(* Logix 5000 project; controller DNP3Master vendor 1 type 14 code 96 rev 19.13; software revision 19.01; part 2 of 5 *)

ADD_ON_INSTRUCTION PSDNP3EventG20V02   (* revision 1.0, vendor ProSoft Technology Inc *)
// Processes DNP3 Event and updates corresponding static DNP3 object. (Report by Exception.)
// G20V02 - Counter - 16bit with Status
VAR_IN_OUT
   EventBuffer : PSDNP3MasterEvent[1]; {required}
END_VAR
VAR_INPUT
   BufferSize : DINT; {required}
   CurrentBufferIndex : DINT; {required}
   Reset : BOOL; {required}
   OutstationNodeAddress : INT; {required}
   OutstationIPAddress0 : INT; {required}
   OutstationIPAddress1 : INT; {required}
   OutstationIPAddress2 : INT; {required}
   OutstationIPAddress3 : INT; {required}
END_VAR
VAR_IN_OUT
   DNP3StaticObject : PSDNP3Counter16WithFlag[1]; {required}
END_VAR
VAR_INPUT
   MaxtElementCount : DINT; {required}
END_VAR
VAR_OUTPUT
   EventsProcessed : DINT; {access Read Only, visible}
   LastElementIndex : DINT; {access Read Only, visible}
   LastValue : DINT; {access Read Only, visible}
   LastStatus : SINT; {access Read Only, visible}
   CurrentUnloadIndex : DINT; {access Read Only, visible}
END_VAR
VAR
   UnloadIndex : DINT; {access None}
   EnableInTemp : BOOL; {access None}
   InitialScan : BOOL; {access None}
   EntryValidForProcessing : BOOL; {access None}
   ElementIndex : DINT; {access None}
   NextIndex : DINT; {access None}
   ResetPulse : BOOL; {access None}
   ResetONS : BOOL; {access None}
END_VAR

ROUTINE Logic   (* ladder *)
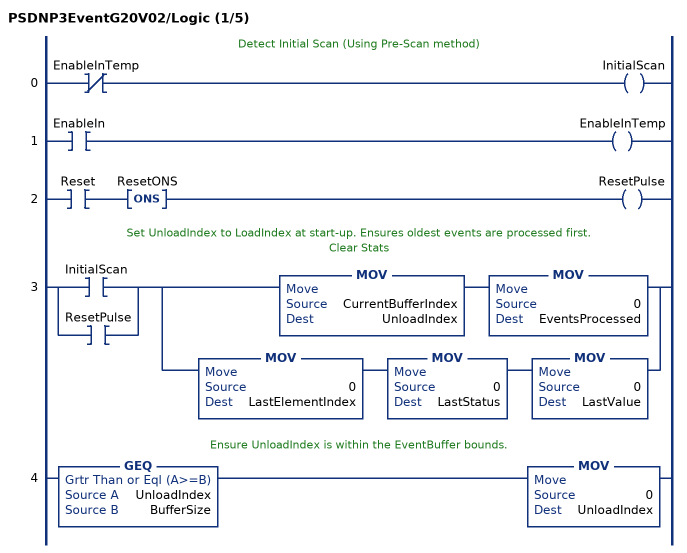
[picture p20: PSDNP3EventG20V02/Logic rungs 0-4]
   // Detect Initial Scan (Using Pre-Scan method)
   0: XIO(EnableInTemp)OTE(InitialScan);
   1: XIC(EnableIn)OTE(EnableInTemp);
   2: XIC(Reset)ONS(ResetONS)OTE(ResetPulse);
   // Set UnloadIndex to LoadIndex at start-up. Ensures oldest events are processed first.
   // Clear Stats
   3: [XIC(InitialScan) ,XIC(ResetPulse) ][MOV(CurrentBufferIndex,UnloadIndex) MOV(0,EventsProcessed) ,MOV(0,LastElementIndex) MOV(0,LastStatus) MOV(0,LastValue) ];
   // Ensure UnloadIndex is within the EventBuffer bounds.
   4: GEQ(UnloadIndex,BufferSize)MOV(0,UnloadIndex);
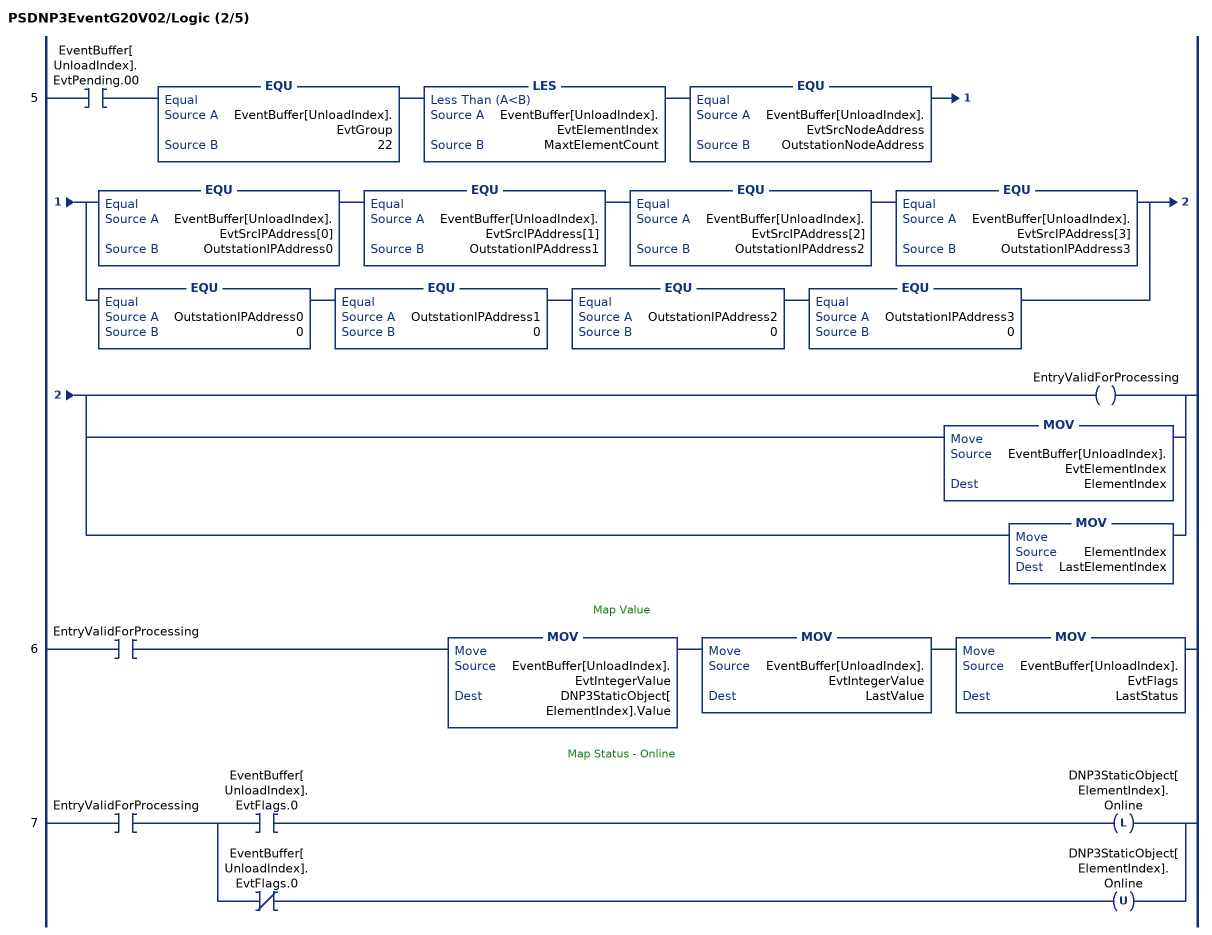
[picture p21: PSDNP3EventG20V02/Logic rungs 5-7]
   5: XIC(EventBuffer[UnloadIndex].EvtPending.00)EQU(EventBuffer[UnloadIndex].EvtGroup,22)LES(EventBuffer[UnloadIndex].EvtElementIndex,MaxtElementCount)EQU(EventBuffer[UnloadIndex].EvtSrcNodeAddress,OutstationNodeAddress)[EQU(EventBuffer[UnloadIndex].EvtSrcIPAddress[0],OutstationIPAddress0) EQU(EventBuffer[UnloadIndex].EvtSrcIPAddress[1],OutstationIPAddress1) EQU(EventBuffer[UnloadIndex].EvtSrcIPAddress[2],OutstationIPAddress2) EQU(EventBuffer[UnloadIndex].EvtSrcIPAddress[3],OutstationIPAddress3) ,EQU(OutstationIPAddress0,0) EQU(OutstationIPAddress1,0) EQU(OutstationIPAddress2,0) EQU(OutstationIPAddress3,0) ][OTE(EntryValidForProcessing) ,MOV(EventBuffer[UnloadIndex].EvtElementIndex,ElementIndex) ,MOV(ElementIndex,LastElementIndex) ];
   // Map Value
   6: XIC(EntryValidForProcessing)MOV(EventBuffer[UnloadIndex].EvtIntegerValue,DNP3StaticObject[ElementIndex].Value)MOV(EventBuffer[UnloadIndex].EvtIntegerValue,LastValue)MOV(EventBuffer[UnloadIndex].EvtFlags,LastStatus);
   // Map Status - Online
   7: XIC(EntryValidForProcessing)[XIC(EventBuffer[UnloadIndex].EvtFlags.0) OTL(DNP3StaticObject[ElementIndex].Online) ,XIO(EventBuffer[UnloadIndex].EvtFlags.0) OTU(DNP3StaticObject[ElementIndex].Online) ];
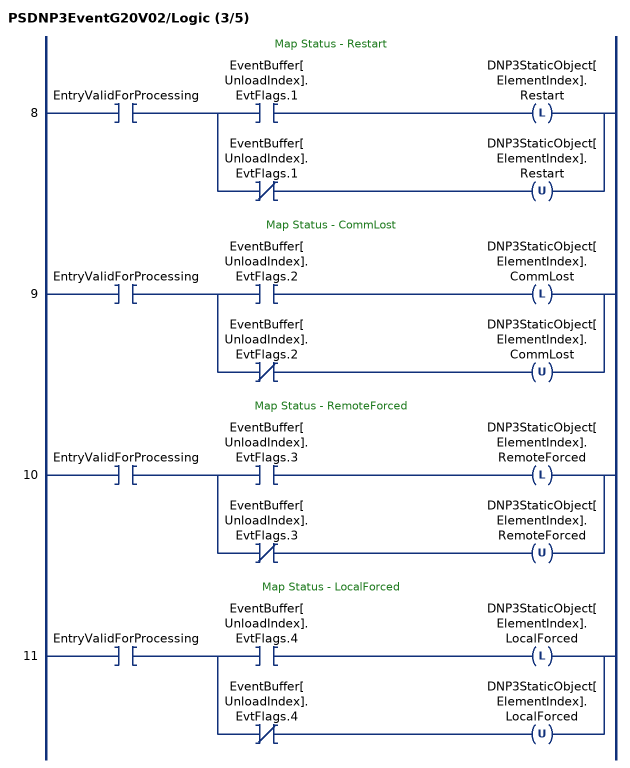
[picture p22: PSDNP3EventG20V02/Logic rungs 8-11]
   // Map Status - Restart
   8: XIC(EntryValidForProcessing)[XIC(EventBuffer[UnloadIndex].EvtFlags.1) OTL(DNP3StaticObject[ElementIndex].Restart) ,XIO(EventBuffer[UnloadIndex].EvtFlags.1) OTU(DNP3StaticObject[ElementIndex].Restart) ];
   // Map Status - CommLost
   9: XIC(EntryValidForProcessing)[XIC(EventBuffer[UnloadIndex].EvtFlags.2) OTL(DNP3StaticObject[ElementIndex].CommLost) ,XIO(EventBuffer[UnloadIndex].EvtFlags.2) OTU(DNP3StaticObject[ElementIndex].CommLost) ];
   // Map Status - RemoteForced
   10: XIC(EntryValidForProcessing)[XIC(EventBuffer[UnloadIndex].EvtFlags.3) OTL(DNP3StaticObject[ElementIndex].RemoteForced) ,XIO(EventBuffer[UnloadIndex].EvtFlags.3) OTU(DNP3StaticObject[ElementIndex].RemoteForced) ];
   // Map Status - LocalForced
   11: XIC(EntryValidForProcessing)[XIC(EventBuffer[UnloadIndex].EvtFlags.4) OTL(DNP3StaticObject[ElementIndex].LocalForced) ,XIO(EventBuffer[UnloadIndex].EvtFlags.4) OTU(DNP3StaticObject[ElementIndex].LocalForced) ];
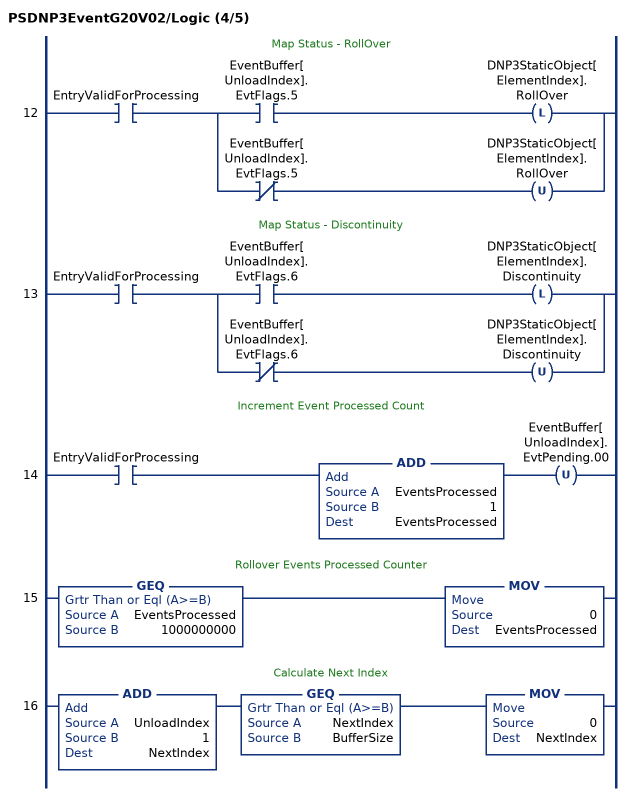
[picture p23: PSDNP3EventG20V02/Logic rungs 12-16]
   // Map Status - RollOver
   12: XIC(EntryValidForProcessing)[XIC(EventBuffer[UnloadIndex].EvtFlags.5) OTL(DNP3StaticObject[ElementIndex].RollOver) ,XIO(EventBuffer[UnloadIndex].EvtFlags.5) OTU(DNP3StaticObject[ElementIndex].RollOver) ];
   // Map Status - Discontinuity
   13: XIC(EntryValidForProcessing)[XIC(EventBuffer[UnloadIndex].EvtFlags.6) OTL(DNP3StaticObject[ElementIndex].Discontinuity) ,XIO(EventBuffer[UnloadIndex].EvtFlags.6) OTU(DNP3StaticObject[ElementIndex].Discontinuity) ];
   // Increment Event Processed Count
   14: XIC(EntryValidForProcessing)ADD(EventsProcessed,1,EventsProcessed)OTU(EventBuffer[UnloadIndex].EvtPending.00);
   // Rollover Events Processed Counter
   15: GEQ(EventsProcessed,1000000000)MOV(0,EventsProcessed);
   // Calculate Next Index
   16: ADD(UnloadIndex,1,NextIndex)GEQ(NextIndex,BufferSize)MOV(0,NextIndex);
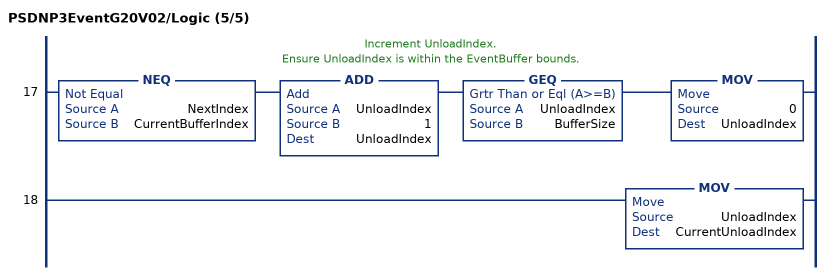
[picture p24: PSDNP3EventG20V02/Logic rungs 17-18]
   // Increment UnloadIndex.
   // Ensure UnloadIndex is within the EventBuffer bounds.
   17: NEQ(NextIndex,CurrentBufferIndex)ADD(UnloadIndex,1,UnloadIndex)GEQ(UnloadIndex,BufferSize)MOV(0,UnloadIndex);
   18: MOV(UnloadIndex,CurrentUnloadIndex);
END_ROUTINE
END_ADD_ON_INSTRUCTION

ADD_ON_INSTRUCTION PSDNP3EventG20V05   (* revision 1.0, vendor ProSoft Technology Inc *)
// Processes DNP3 Event and updates corresponding static DNP3 object. (Report by Exception.)
// G20V05 - Counter - 32bit no Status
VAR_IN_OUT
   EventBuffer : PSDNP3MasterEvent[1]; {required}
END_VAR
VAR_INPUT
   BufferSize : DINT; {required}
   CurrentBufferIndex : DINT; {required}
   Reset : BOOL; {required}
   OutstationNodeAddress : INT; {required}
   OutstationIPAddress0 : INT; {required}
   OutstationIPAddress1 : INT; {required}
   OutstationIPAddress2 : INT; {required}
   OutstationIPAddress3 : INT; {required}
END_VAR
VAR_IN_OUT
   DNP3StaticObject : DINT[1]; {required}
END_VAR
VAR_INPUT
   MaxtElementCount : DINT; {required}
END_VAR
VAR_OUTPUT
   EventsProcessed : DINT; {access Read Only, visible}
   LastElementIndex : DINT; {access Read Only, visible}
   LastValue : DINT; {access Read Only, visible}
   LastStatus : SINT; {access Read Only, visible}
   CurrentUnloadIndex : DINT; {access Read Only, visible}
END_VAR
VAR
   UnloadIndex : DINT; {access None}
   EnableInTemp : BOOL; {access None}
   InitialScan : BOOL; {access None}
   EntryValidForProcessing : BOOL; {access None}
   ElementIndex : DINT; {access None}
   NextIndex : DINT; {access None}
   ResetPulse : BOOL; {access None}
   ResetONS : BOOL; {access None}
END_VAR

ROUTINE Logic   (* ladder *)
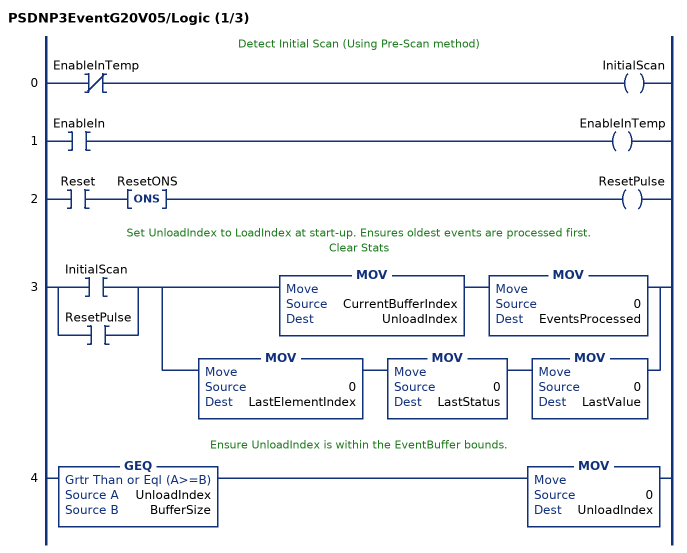
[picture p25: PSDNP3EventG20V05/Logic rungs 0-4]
   // Detect Initial Scan (Using Pre-Scan method)
   0: XIO(EnableInTemp)OTE(InitialScan);
   1: XIC(EnableIn)OTE(EnableInTemp);
   2: XIC(Reset)ONS(ResetONS)OTE(ResetPulse);
   // Set UnloadIndex to LoadIndex at start-up. Ensures oldest events are processed first.
   // Clear Stats
   3: [XIC(InitialScan) ,XIC(ResetPulse) ][MOV(CurrentBufferIndex,UnloadIndex) MOV(0,EventsProcessed) ,MOV(0,LastElementIndex) MOV(0,LastStatus) MOV(0,LastValue) ];
   // Ensure UnloadIndex is within the EventBuffer bounds.
   4: GEQ(UnloadIndex,BufferSize)MOV(0,UnloadIndex);
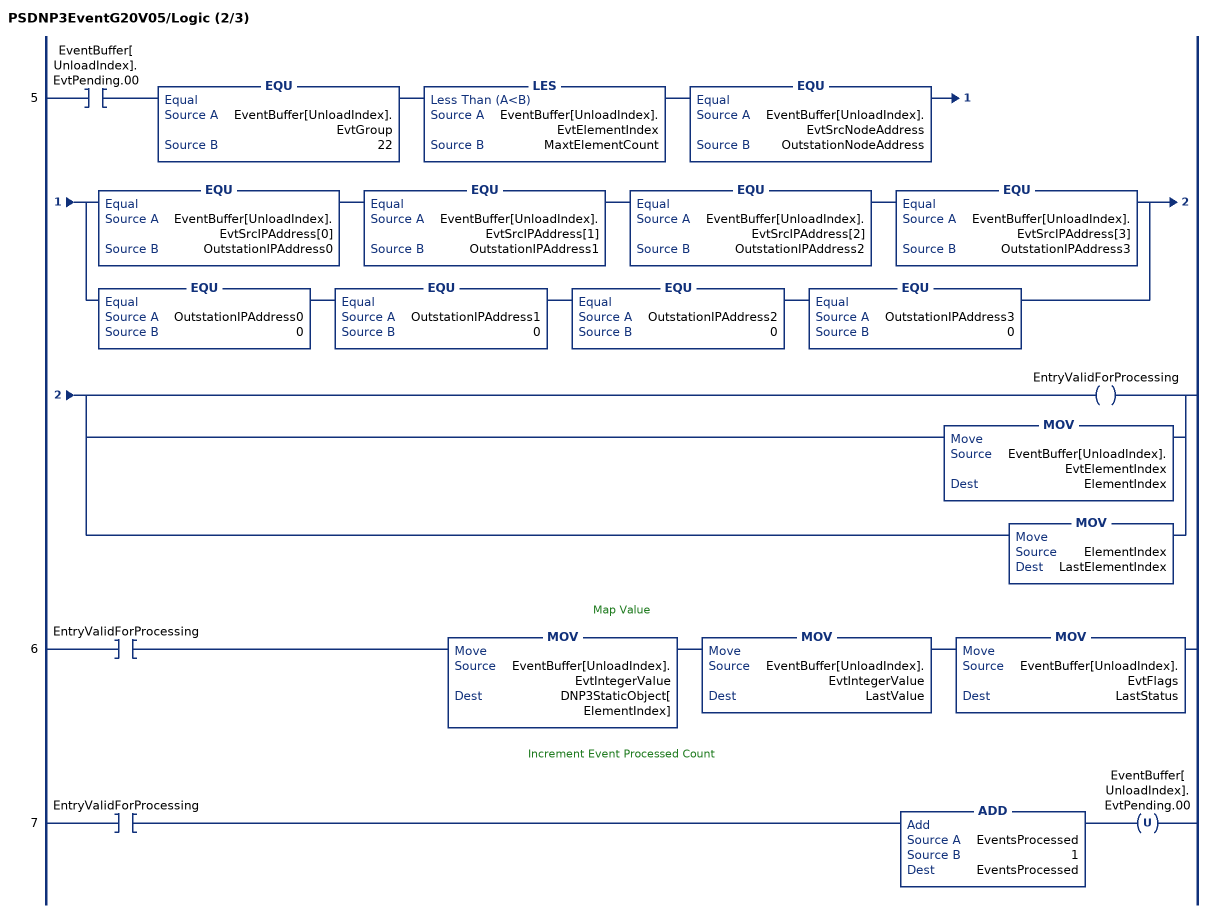
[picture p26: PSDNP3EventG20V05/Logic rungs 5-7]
   5: XIC(EventBuffer[UnloadIndex].EvtPending.00)EQU(EventBuffer[UnloadIndex].EvtGroup,22)LES(EventBuffer[UnloadIndex].EvtElementIndex,MaxtElementCount)EQU(EventBuffer[UnloadIndex].EvtSrcNodeAddress,OutstationNodeAddress)[EQU(EventBuffer[UnloadIndex].EvtSrcIPAddress[0],OutstationIPAddress0) EQU(EventBuffer[UnloadIndex].EvtSrcIPAddress[1],OutstationIPAddress1) EQU(EventBuffer[UnloadIndex].EvtSrcIPAddress[2],OutstationIPAddress2) EQU(EventBuffer[UnloadIndex].EvtSrcIPAddress[3],OutstationIPAddress3) ,EQU(OutstationIPAddress0,0) EQU(OutstationIPAddress1,0) EQU(OutstationIPAddress2,0) EQU(OutstationIPAddress3,0) ][OTE(EntryValidForProcessing) ,MOV(EventBuffer[UnloadIndex].EvtElementIndex,ElementIndex) ,MOV(ElementIndex,LastElementIndex) ];
   // Map Value
   6: XIC(EntryValidForProcessing)MOV(EventBuffer[UnloadIndex].EvtIntegerValue,DNP3StaticObject[ElementIndex])MOV(EventBuffer[UnloadIndex].EvtIntegerValue,LastValue)MOV(EventBuffer[UnloadIndex].EvtFlags,LastStatus);
   // Increment Event Processed Count
   7: XIC(EntryValidForProcessing)ADD(EventsProcessed,1,EventsProcessed)OTU(EventBuffer[UnloadIndex].EvtPending.00);
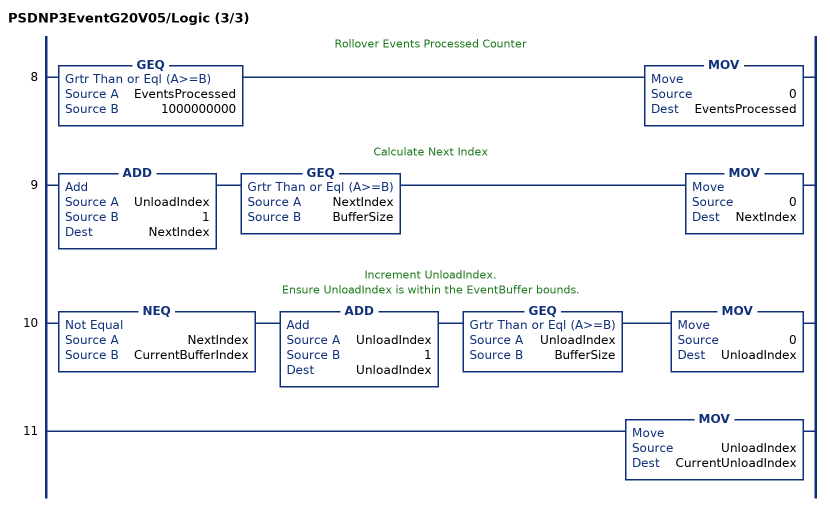
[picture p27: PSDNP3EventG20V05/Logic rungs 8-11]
   // Rollover Events Processed Counter
   8: GEQ(EventsProcessed,1000000000)MOV(0,EventsProcessed);
   // Calculate Next Index
   9: ADD(UnloadIndex,1,NextIndex)GEQ(NextIndex,BufferSize)MOV(0,NextIndex);
   // Increment UnloadIndex.
   // Ensure UnloadIndex is within the EventBuffer bounds.
   10: NEQ(NextIndex,CurrentBufferIndex)ADD(UnloadIndex,1,UnloadIndex)GEQ(UnloadIndex,BufferSize)MOV(0,UnloadIndex);
   11: MOV(UnloadIndex,CurrentUnloadIndex);
END_ROUTINE
END_ADD_ON_INSTRUCTION

ADD_ON_INSTRUCTION PSDNP3EventG20V06   (* revision 1.0, vendor ProSoft Technology Inc *)
// Processes DNP3 Event and updates corresponding static DNP3 object. (Report by Exception.)
// G20V06 - Counter - 16bit no Status
VAR_IN_OUT
   EventBuffer : PSDNP3MasterEvent[1]; {required}
END_VAR
VAR_INPUT
   BufferSize : DINT; {required}
   CurrentBufferIndex : DINT; {required}
   Reset : BOOL; {required}
   OutstationNodeAddress : INT; {required}
   OutstationIPAddress0 : INT; {required}
   OutstationIPAddress1 : INT; {required}
   OutstationIPAddress2 : INT; {required}
   OutstationIPAddress3 : INT; {required}
END_VAR
VAR_IN_OUT
   DNP3StaticObject : INT[1]; {required}
END_VAR
VAR_INPUT
   MaxtElementCount : DINT; {required}
END_VAR
VAR_OUTPUT
   EventsProcessed : DINT; {access Read Only, visible}
   LastElementIndex : DINT; {access Read Only, visible}
   LastValue : DINT; {access Read Only, visible}
   LastStatus : SINT; {access Read Only, visible}
   CurrentUnloadIndex : DINT; {access Read Only, visible}
END_VAR
VAR
   UnloadIndex : DINT; {access None}
   EnableInTemp : BOOL; {access None}
   InitialScan : BOOL; {access None}
   EntryValidForProcessing : BOOL; {access None}
   ElementIndex : DINT; {access None}
   NextIndex : DINT; {access None}
   ResetPulse : BOOL; {access None}
   ResetONS : BOOL; {access None}
END_VAR

ROUTINE Logic   (* ladder *)
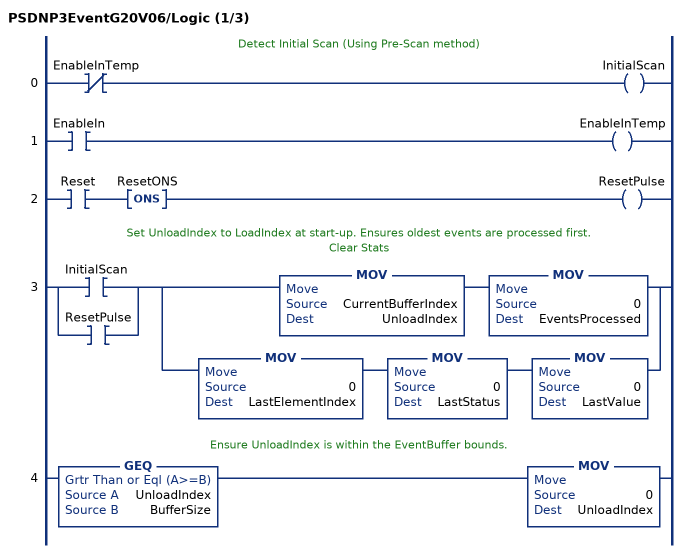
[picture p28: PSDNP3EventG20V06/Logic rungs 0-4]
   // Detect Initial Scan (Using Pre-Scan method)
   0: XIO(EnableInTemp)OTE(InitialScan);
   1: XIC(EnableIn)OTE(EnableInTemp);
   2: XIC(Reset)ONS(ResetONS)OTE(ResetPulse);
   // Set UnloadIndex to LoadIndex at start-up. Ensures oldest events are processed first.
   // Clear Stats
   3: [XIC(InitialScan) ,XIC(ResetPulse) ][MOV(CurrentBufferIndex,UnloadIndex) MOV(0,EventsProcessed) ,MOV(0,LastElementIndex) MOV(0,LastStatus) MOV(0,LastValue) ];
   // Ensure UnloadIndex is within the EventBuffer bounds.
   4: GEQ(UnloadIndex,BufferSize)MOV(0,UnloadIndex);
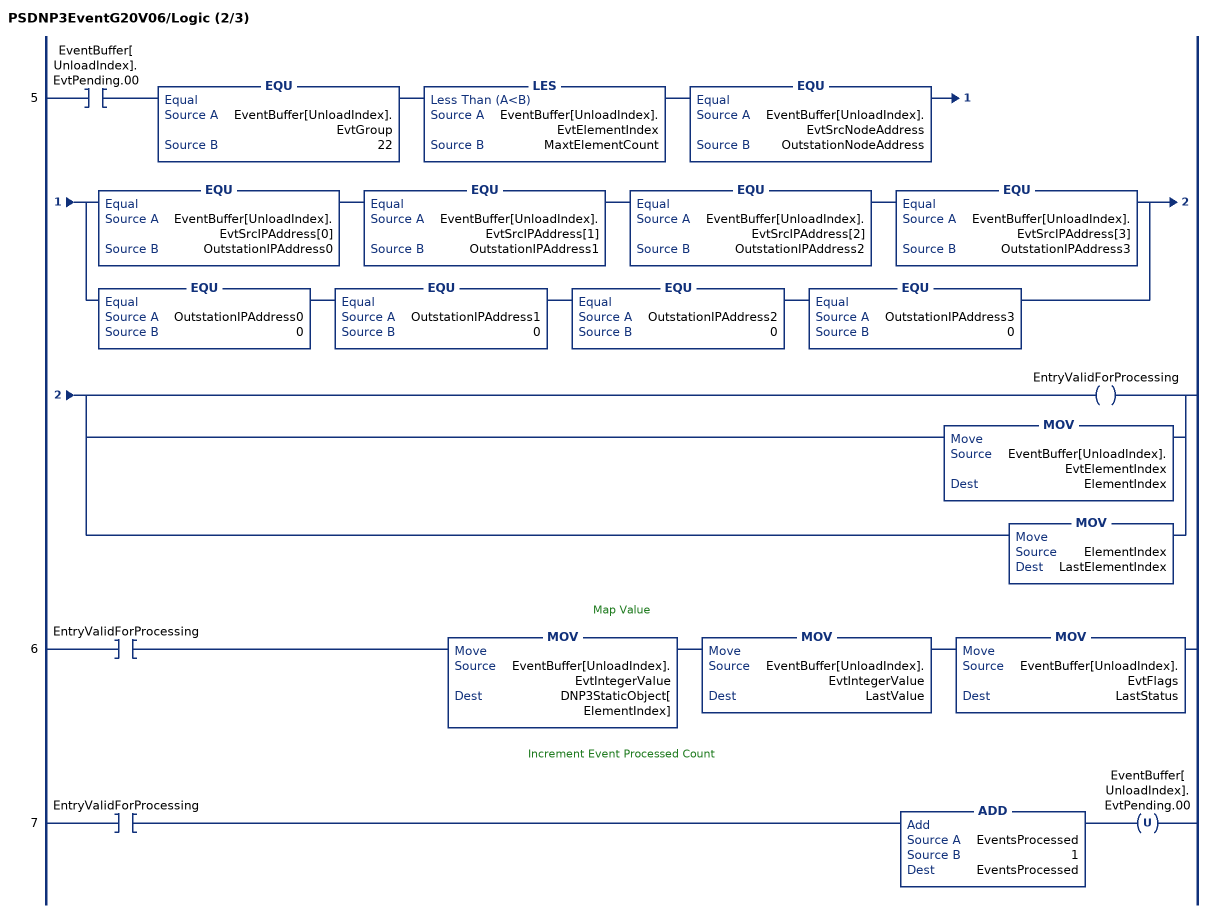
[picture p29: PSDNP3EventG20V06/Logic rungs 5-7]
   5: XIC(EventBuffer[UnloadIndex].EvtPending.00)EQU(EventBuffer[UnloadIndex].EvtGroup,22)LES(EventBuffer[UnloadIndex].EvtElementIndex,MaxtElementCount)EQU(EventBuffer[UnloadIndex].EvtSrcNodeAddress,OutstationNodeAddress)[EQU(EventBuffer[UnloadIndex].EvtSrcIPAddress[0],OutstationIPAddress0) EQU(EventBuffer[UnloadIndex].EvtSrcIPAddress[1],OutstationIPAddress1) EQU(EventBuffer[UnloadIndex].EvtSrcIPAddress[2],OutstationIPAddress2) EQU(EventBuffer[UnloadIndex].EvtSrcIPAddress[3],OutstationIPAddress3) ,EQU(OutstationIPAddress0,0) EQU(OutstationIPAddress1,0) EQU(OutstationIPAddress2,0) EQU(OutstationIPAddress3,0) ][OTE(EntryValidForProcessing) ,MOV(EventBuffer[UnloadIndex].EvtElementIndex,ElementIndex) ,MOV(ElementIndex,LastElementIndex) ];
   // Map Value
   6: XIC(EntryValidForProcessing)MOV(EventBuffer[UnloadIndex].EvtIntegerValue,DNP3StaticObject[ElementIndex])MOV(EventBuffer[UnloadIndex].EvtIntegerValue,LastValue)MOV(EventBuffer[UnloadIndex].EvtFlags,LastStatus);
   // Increment Event Processed Count
   7: XIC(EntryValidForProcessing)ADD(EventsProcessed,1,EventsProcessed)OTU(EventBuffer[UnloadIndex].EvtPending.00);
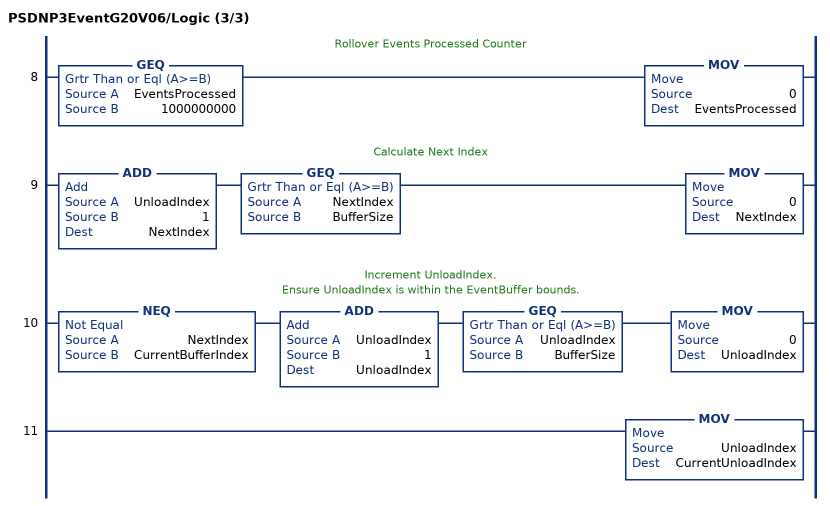
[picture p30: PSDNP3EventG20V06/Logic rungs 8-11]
   // Rollover Events Processed Counter
   8: GEQ(EventsProcessed,1000000000)MOV(0,EventsProcessed);
   // Calculate Next Index
   9: ADD(UnloadIndex,1,NextIndex)GEQ(NextIndex,BufferSize)MOV(0,NextIndex);
   // Increment UnloadIndex.
   // Ensure UnloadIndex is within the EventBuffer bounds.
   10: NEQ(NextIndex,CurrentBufferIndex)ADD(UnloadIndex,1,UnloadIndex)GEQ(UnloadIndex,BufferSize)MOV(0,UnloadIndex);
   11: MOV(UnloadIndex,CurrentUnloadIndex);
END_ROUTINE
END_ADD_ON_INSTRUCTION

ADD_ON_INSTRUCTION PSDNP3EventG21V01   (* revision 1.0, vendor ProSoft Technology Inc *)
// Processes DNP3 Event and updates corresponding static DNP3 object. (Report by Exception.)
// G21V01 - Frozen Counter - 32bit with Status
VAR_IN_OUT
   EventBuffer : PSDNP3MasterEvent[1]; {required}
END_VAR
VAR_INPUT
   BufferSize : DINT; {required}
   CurrentBufferIndex : DINT; {required}
   Reset : BOOL; {required}
   OutstationNodeAddress : INT; {required}
   OutstationIPAddress0 : INT; {required}
   OutstationIPAddress1 : INT; {required}
   OutstationIPAddress2 : INT; {required}
   OutstationIPAddress3 : INT; {required}
END_VAR
VAR_IN_OUT
   DNP3StaticObject : PSDNP3FrozenCounter32WithFlag[1]; {required}
END_VAR
VAR_INPUT
   MaxtElementCount : DINT; {required}
END_VAR
VAR_OUTPUT
   EventsProcessed : DINT; {access Read Only, visible}
   LastElementIndex : DINT; {access Read Only, visible}
   LastValue : DINT; {access Read Only, visible}
   LastStatus : SINT; {access Read Only, visible}
   CurrentUnloadIndex : DINT; {access Read Only, visible}
END_VAR
VAR
   UnloadIndex : DINT; {access None}
   EnableInTemp : BOOL; {access None}
   InitialScan : BOOL; {access None}
   EntryValidForProcessing : BOOL; {access None}
   ElementIndex : DINT; {access None}
   NextIndex : DINT; {access None}
   ResetPulse : BOOL; {access None}
   ResetONS : BOOL; {access None}
END_VAR

ROUTINE Logic   (* ladder *)
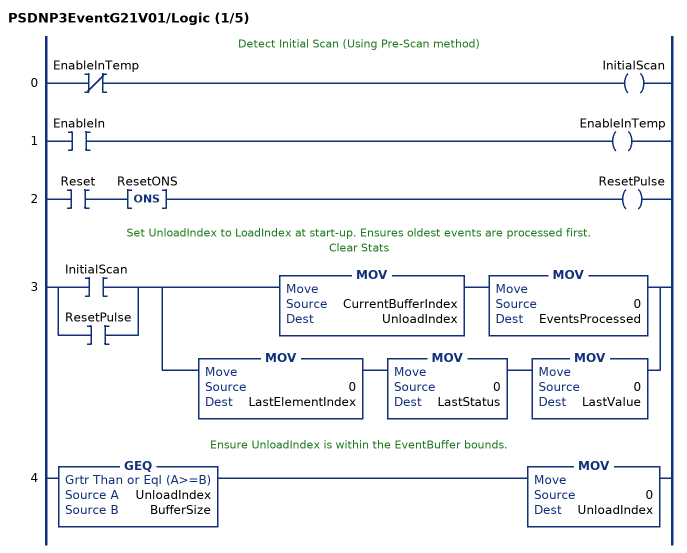
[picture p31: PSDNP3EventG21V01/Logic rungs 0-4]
   // Detect Initial Scan (Using Pre-Scan method)
   0: XIO(EnableInTemp)OTE(InitialScan);
   1: XIC(EnableIn)OTE(EnableInTemp);
   2: XIC(Reset)ONS(ResetONS)OTE(ResetPulse);
   // Set UnloadIndex to LoadIndex at start-up. Ensures oldest events are processed first.
   // Clear Stats
   3: [XIC(InitialScan) ,XIC(ResetPulse) ][MOV(CurrentBufferIndex,UnloadIndex) MOV(0,EventsProcessed) ,MOV(0,LastElementIndex) MOV(0,LastStatus) MOV(0,LastValue) ];
   // Ensure UnloadIndex is within the EventBuffer bounds.
   4: GEQ(UnloadIndex,BufferSize)MOV(0,UnloadIndex);
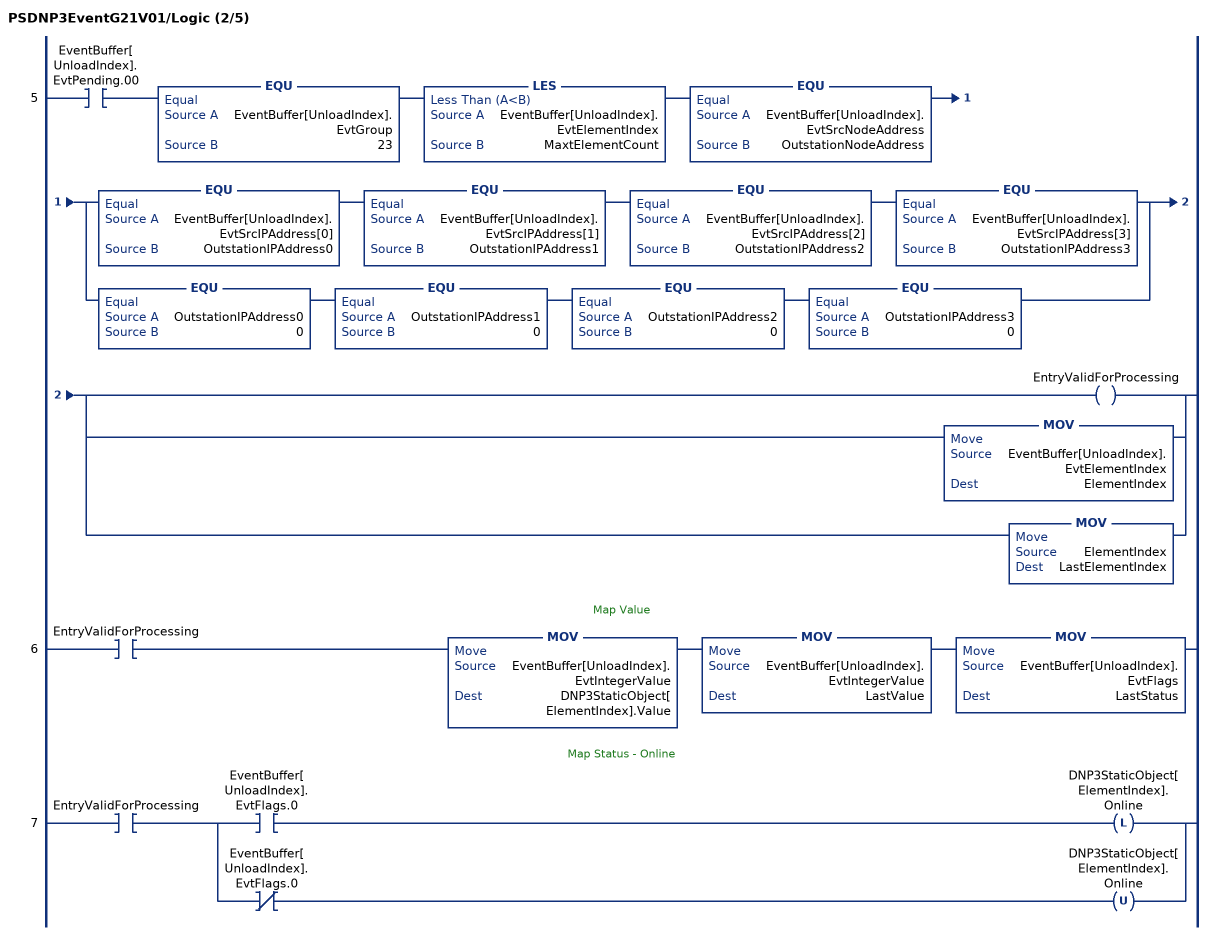
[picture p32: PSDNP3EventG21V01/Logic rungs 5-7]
   5: XIC(EventBuffer[UnloadIndex].EvtPending.00)EQU(EventBuffer[UnloadIndex].EvtGroup,23)LES(EventBuffer[UnloadIndex].EvtElementIndex,MaxtElementCount)EQU(EventBuffer[UnloadIndex].EvtSrcNodeAddress,OutstationNodeAddress)[EQU(EventBuffer[UnloadIndex].EvtSrcIPAddress[0],OutstationIPAddress0) EQU(EventBuffer[UnloadIndex].EvtSrcIPAddress[1],OutstationIPAddress1) EQU(EventBuffer[UnloadIndex].EvtSrcIPAddress[2],OutstationIPAddress2) EQU(EventBuffer[UnloadIndex].EvtSrcIPAddress[3],OutstationIPAddress3) ,EQU(OutstationIPAddress0,0) EQU(OutstationIPAddress1,0) EQU(OutstationIPAddress2,0) EQU(OutstationIPAddress3,0) ][OTE(EntryValidForProcessing) ,MOV(EventBuffer[UnloadIndex].EvtElementIndex,ElementIndex) ,MOV(ElementIndex,LastElementIndex) ];
   // Map Value
   6: XIC(EntryValidForProcessing)MOV(EventBuffer[UnloadIndex].EvtIntegerValue,DNP3StaticObject[ElementIndex].Value)MOV(EventBuffer[UnloadIndex].EvtIntegerValue,LastValue)MOV(EventBuffer[UnloadIndex].EvtFlags,LastStatus);
   // Map Status - Online
   7: XIC(EntryValidForProcessing)[XIC(EventBuffer[UnloadIndex].EvtFlags.0) OTL(DNP3StaticObject[ElementIndex].Online) ,XIO(EventBuffer[UnloadIndex].EvtFlags.0) OTU(DNP3StaticObject[ElementIndex].Online) ];
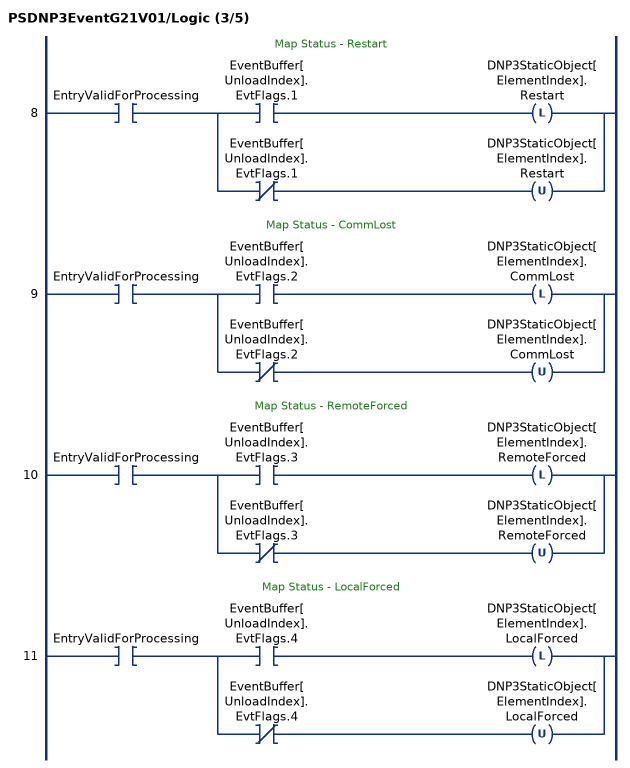
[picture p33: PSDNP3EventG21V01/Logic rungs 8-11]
   // Map Status - Restart
   8: XIC(EntryValidForProcessing)[XIC(EventBuffer[UnloadIndex].EvtFlags.1) OTL(DNP3StaticObject[ElementIndex].Restart) ,XIO(EventBuffer[UnloadIndex].EvtFlags.1) OTU(DNP3StaticObject[ElementIndex].Restart) ];
   // Map Status - CommLost
   9: XIC(EntryValidForProcessing)[XIC(EventBuffer[UnloadIndex].EvtFlags.2) OTL(DNP3StaticObject[ElementIndex].CommLost) ,XIO(EventBuffer[UnloadIndex].EvtFlags.2) OTU(DNP3StaticObject[ElementIndex].CommLost) ];
   // Map Status - RemoteForced
   10: XIC(EntryValidForProcessing)[XIC(EventBuffer[UnloadIndex].EvtFlags.3) OTL(DNP3StaticObject[ElementIndex].RemoteForced) ,XIO(EventBuffer[UnloadIndex].EvtFlags.3) OTU(DNP3StaticObject[ElementIndex].RemoteForced) ];
   // Map Status - LocalForced
   11: XIC(EntryValidForProcessing)[XIC(EventBuffer[UnloadIndex].EvtFlags.4) OTL(DNP3StaticObject[ElementIndex].LocalForced) ,XIO(EventBuffer[UnloadIndex].EvtFlags.4) OTU(DNP3StaticObject[ElementIndex].LocalForced) ];
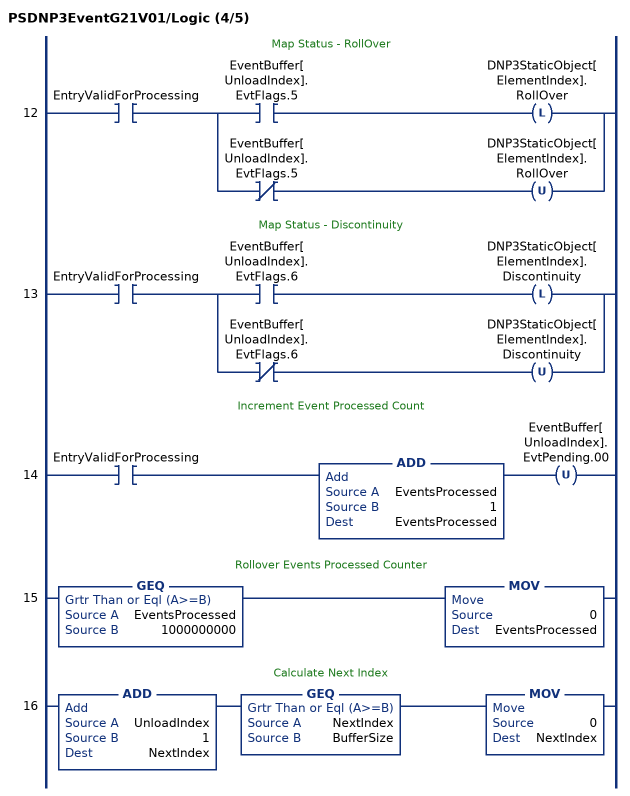
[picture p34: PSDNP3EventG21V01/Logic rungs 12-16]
   // Map Status - RollOver
   12: XIC(EntryValidForProcessing)[XIC(EventBuffer[UnloadIndex].EvtFlags.5) OTL(DNP3StaticObject[ElementIndex].RollOver) ,XIO(EventBuffer[UnloadIndex].EvtFlags.5) OTU(DNP3StaticObject[ElementIndex].RollOver) ];
   // Map Status - Discontinuity
   13: XIC(EntryValidForProcessing)[XIC(EventBuffer[UnloadIndex].EvtFlags.6) OTL(DNP3StaticObject[ElementIndex].Discontinuity) ,XIO(EventBuffer[UnloadIndex].EvtFlags.6) OTU(DNP3StaticObject[ElementIndex].Discontinuity) ];
   // Increment Event Processed Count
   14: XIC(EntryValidForProcessing)ADD(EventsProcessed,1,EventsProcessed)OTU(EventBuffer[UnloadIndex].EvtPending.00);
   // Rollover Events Processed Counter
   15: GEQ(EventsProcessed,1000000000)MOV(0,EventsProcessed);
   // Calculate Next Index
   16: ADD(UnloadIndex,1,NextIndex)GEQ(NextIndex,BufferSize)MOV(0,NextIndex);
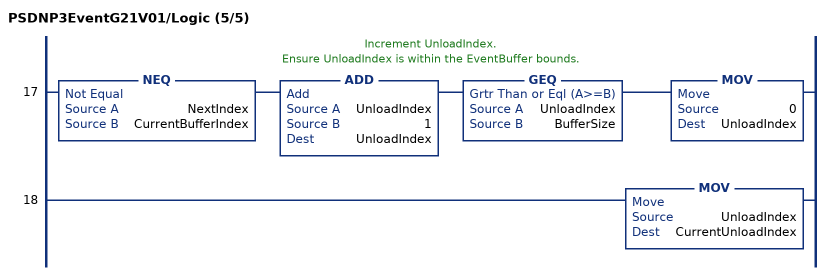
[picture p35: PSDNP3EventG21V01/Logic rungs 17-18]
   // Increment UnloadIndex.
   // Ensure UnloadIndex is within the EventBuffer bounds.
   17: NEQ(NextIndex,CurrentBufferIndex)ADD(UnloadIndex,1,UnloadIndex)GEQ(UnloadIndex,BufferSize)MOV(0,UnloadIndex);
   18: MOV(UnloadIndex,CurrentUnloadIndex);
END_ROUTINE
END_ADD_ON_INSTRUCTION

ADD_ON_INSTRUCTION PSDNP3EventG21V02   (* revision 1.0, vendor ProSoft Technology Inc *)
// Processes DNP3 Event and updates corresponding static DNP3 object. (Report by Exception.)
// G21V02 - Frozen Counter - 16bit with Status
VAR_IN_OUT
   EventBuffer : PSDNP3MasterEvent[1]; {required}
END_VAR
VAR_INPUT
   BufferSize : DINT; {required}
   CurrentBufferIndex : DINT; {required}
   Reset : BOOL; {required}
   OutstationNodeAddress : INT; {required}
   OutstationIPAddress0 : INT; {required}
   OutstationIPAddress1 : INT; {required}
   OutstationIPAddress2 : INT; {required}
   OutstationIPAddress3 : INT; {required}
END_VAR
VAR_IN_OUT
   DNP3StaticObject : PSDNP3FrozenCounter16WithFlag[1]; {required}
END_VAR
VAR_INPUT
   MaxtElementCount : DINT; {required}
END_VAR
VAR_OUTPUT
   EventsProcessed : DINT; {access Read Only, visible}
   LastElementIndex : DINT; {access Read Only, visible}
   LastValue : DINT; {access Read Only, visible}
   LastStatus : SINT; {access Read Only, visible}
   CurrentUnloadIndex : DINT; {access Read Only, visible}
END_VAR
VAR
   UnloadIndex : DINT; {access None}
   EnableInTemp : BOOL; {access None}
   InitialScan : BOOL; {access None}
   EntryValidForProcessing : BOOL; {access None}
   ElementIndex : DINT; {access None}
   NextIndex : DINT; {access None}
   ResetPulse : BOOL; {access None}
   ResetONS : BOOL; {access None}
END_VAR

ROUTINE Logic   (* ladder *)
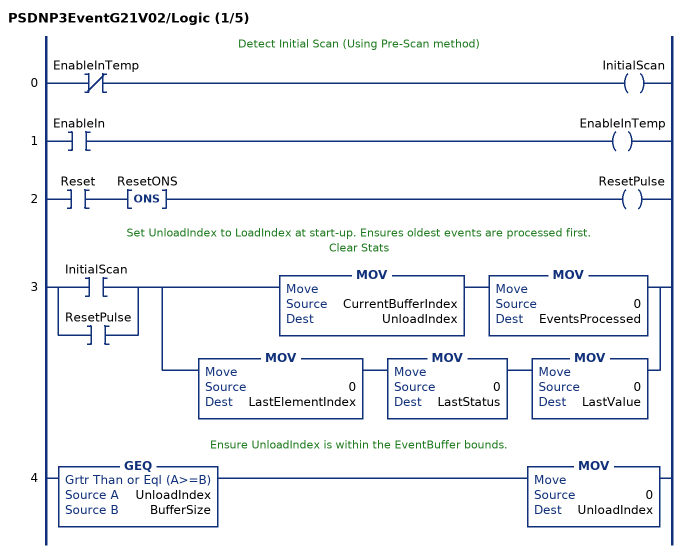
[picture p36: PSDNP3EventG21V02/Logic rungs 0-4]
   // Detect Initial Scan (Using Pre-Scan method)
   0: XIO(EnableInTemp)OTE(InitialScan);
   1: XIC(EnableIn)OTE(EnableInTemp);
   2: XIC(Reset)ONS(ResetONS)OTE(ResetPulse);
   // Set UnloadIndex to LoadIndex at start-up. Ensures oldest events are processed first.
   // Clear Stats
   3: [XIC(InitialScan) ,XIC(ResetPulse) ][MOV(CurrentBufferIndex,UnloadIndex) MOV(0,EventsProcessed) ,MOV(0,LastElementIndex) MOV(0,LastStatus) MOV(0,LastValue) ];
   // Ensure UnloadIndex is within the EventBuffer bounds.
   4: GEQ(UnloadIndex,BufferSize)MOV(0,UnloadIndex);
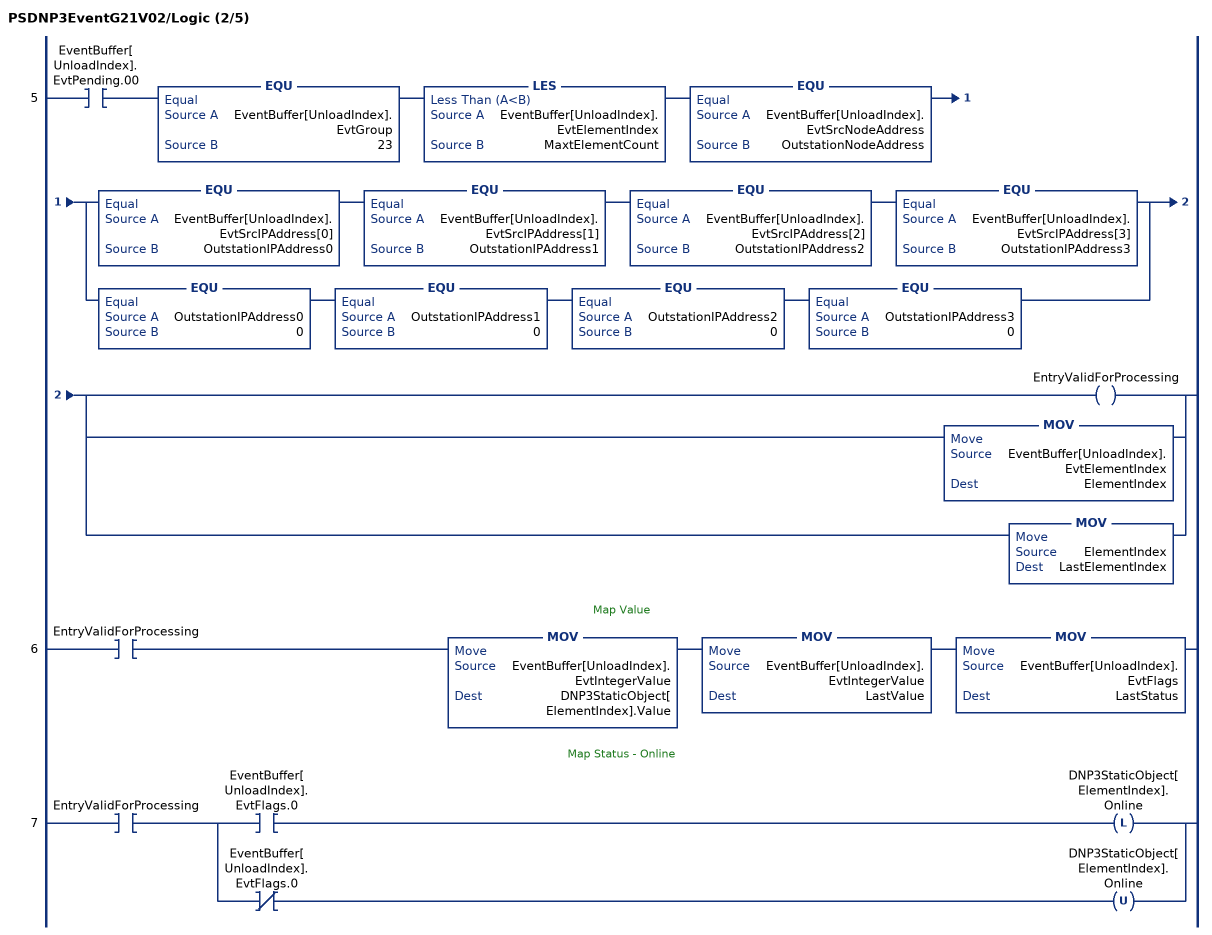
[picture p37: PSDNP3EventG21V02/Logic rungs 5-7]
   5: XIC(EventBuffer[UnloadIndex].EvtPending.00)EQU(EventBuffer[UnloadIndex].EvtGroup,23)LES(EventBuffer[UnloadIndex].EvtElementIndex,MaxtElementCount)EQU(EventBuffer[UnloadIndex].EvtSrcNodeAddress,OutstationNodeAddress)[EQU(EventBuffer[UnloadIndex].EvtSrcIPAddress[0],OutstationIPAddress0) EQU(EventBuffer[UnloadIndex].EvtSrcIPAddress[1],OutstationIPAddress1) EQU(EventBuffer[UnloadIndex].EvtSrcIPAddress[2],OutstationIPAddress2) EQU(EventBuffer[UnloadIndex].EvtSrcIPAddress[3],OutstationIPAddress3) ,EQU(OutstationIPAddress0,0) EQU(OutstationIPAddress1,0) EQU(OutstationIPAddress2,0) EQU(OutstationIPAddress3,0) ][OTE(EntryValidForProcessing) ,MOV(EventBuffer[UnloadIndex].EvtElementIndex,ElementIndex) ,MOV(ElementIndex,LastElementIndex) ];
   // Map Value
   6: XIC(EntryValidForProcessing)MOV(EventBuffer[UnloadIndex].EvtIntegerValue,DNP3StaticObject[ElementIndex].Value)MOV(EventBuffer[UnloadIndex].EvtIntegerValue,LastValue)MOV(EventBuffer[UnloadIndex].EvtFlags,LastStatus);
   // Map Status - Online
   7: XIC(EntryValidForProcessing)[XIC(EventBuffer[UnloadIndex].EvtFlags.0) OTL(DNP3StaticObject[ElementIndex].Online) ,XIO(EventBuffer[UnloadIndex].EvtFlags.0) OTU(DNP3StaticObject[ElementIndex].Online) ];
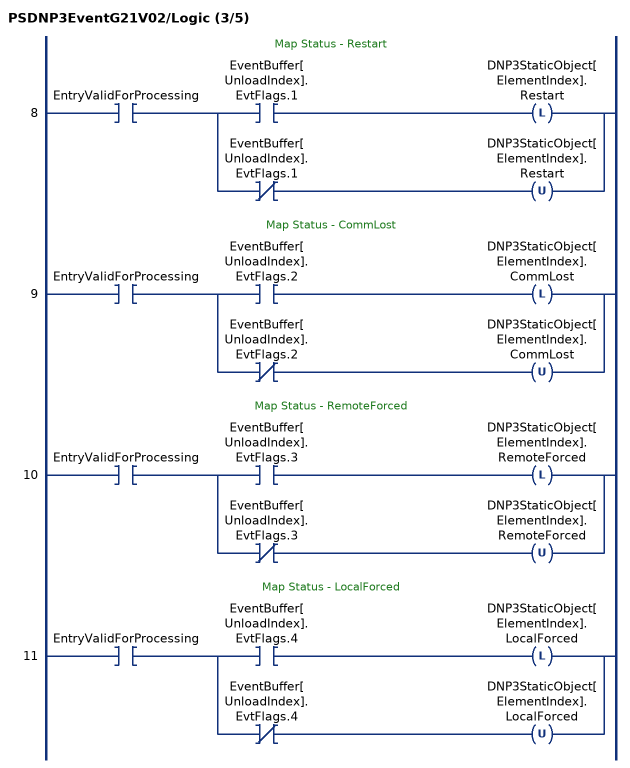
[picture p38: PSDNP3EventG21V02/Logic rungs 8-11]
   // Map Status - Restart
   8: XIC(EntryValidForProcessing)[XIC(EventBuffer[UnloadIndex].EvtFlags.1) OTL(DNP3StaticObject[ElementIndex].Restart) ,XIO(EventBuffer[UnloadIndex].EvtFlags.1) OTU(DNP3StaticObject[ElementIndex].Restart) ];
   // Map Status - CommLost
   9: XIC(EntryValidForProcessing)[XIC(EventBuffer[UnloadIndex].EvtFlags.2) OTL(DNP3StaticObject[ElementIndex].CommLost) ,XIO(EventBuffer[UnloadIndex].EvtFlags.2) OTU(DNP3StaticObject[ElementIndex].CommLost) ];
   // Map Status - RemoteForced
   10: XIC(EntryValidForProcessing)[XIC(EventBuffer[UnloadIndex].EvtFlags.3) OTL(DNP3StaticObject[ElementIndex].RemoteForced) ,XIO(EventBuffer[UnloadIndex].EvtFlags.3) OTU(DNP3StaticObject[ElementIndex].RemoteForced) ];
   // Map Status - LocalForced
   11: XIC(EntryValidForProcessing)[XIC(EventBuffer[UnloadIndex].EvtFlags.4) OTL(DNP3StaticObject[ElementIndex].LocalForced) ,XIO(EventBuffer[UnloadIndex].EvtFlags.4) OTU(DNP3StaticObject[ElementIndex].LocalForced) ];
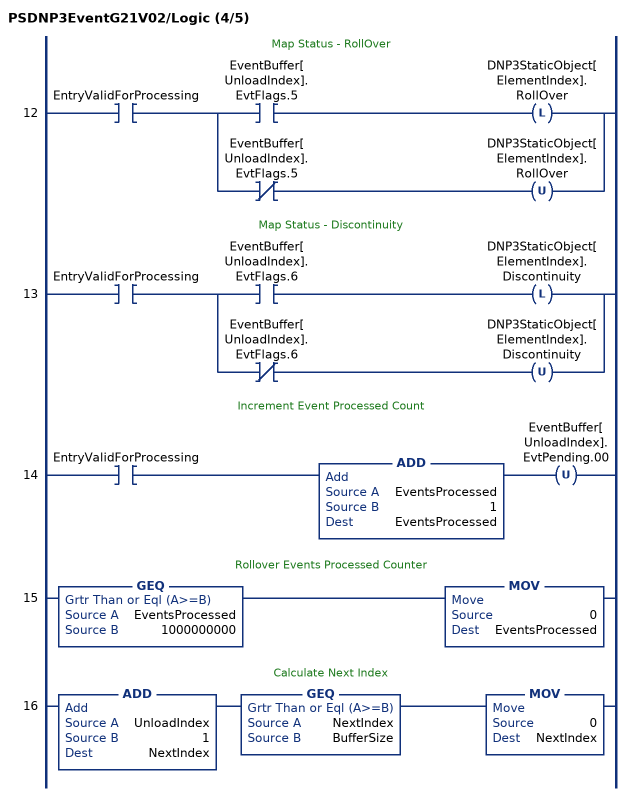
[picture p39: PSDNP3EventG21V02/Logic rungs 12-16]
   // Map Status - RollOver
   12: XIC(EntryValidForProcessing)[XIC(EventBuffer[UnloadIndex].EvtFlags.5) OTL(DNP3StaticObject[ElementIndex].RollOver) ,XIO(EventBuffer[UnloadIndex].EvtFlags.5) OTU(DNP3StaticObject[ElementIndex].RollOver) ];
   // Map Status - Discontinuity
   13: XIC(EntryValidForProcessing)[XIC(EventBuffer[UnloadIndex].EvtFlags.6) OTL(DNP3StaticObject[ElementIndex].Discontinuity) ,XIO(EventBuffer[UnloadIndex].EvtFlags.6) OTU(DNP3StaticObject[ElementIndex].Discontinuity) ];
   // Increment Event Processed Count
   14: XIC(EntryValidForProcessing)ADD(EventsProcessed,1,EventsProcessed)OTU(EventBuffer[UnloadIndex].EvtPending.00);
   // Rollover Events Processed Counter
   15: GEQ(EventsProcessed,1000000000)MOV(0,EventsProcessed);
   // Calculate Next Index
   16: ADD(UnloadIndex,1,NextIndex)GEQ(NextIndex,BufferSize)MOV(0,NextIndex);
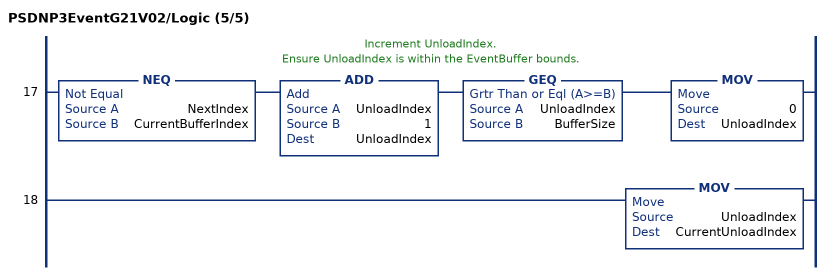
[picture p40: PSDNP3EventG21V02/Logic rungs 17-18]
   // Increment UnloadIndex.
   // Ensure UnloadIndex is within the EventBuffer bounds.
   17: NEQ(NextIndex,CurrentBufferIndex)ADD(UnloadIndex,1,UnloadIndex)GEQ(UnloadIndex,BufferSize)MOV(0,UnloadIndex);
   18: MOV(UnloadIndex,CurrentUnloadIndex);
END_ROUTINE
END_ADD_ON_INSTRUCTION
